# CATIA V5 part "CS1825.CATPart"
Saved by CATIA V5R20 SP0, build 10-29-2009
Part number: CS1825
Revision: 4
Definition: design
Nomenclature: CS1825
Source: made
Description: NOT SPECIFIED
Bounding box of the stored display mesh (mm): x -23.825 to 24, y -24 to 24, z -45 to 12
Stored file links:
  C:\Users\Raffaele\Desktop\3D X SITO CF\BOLEX\20-TILTED COLUMN SUPPORT\CS1825.CATPart
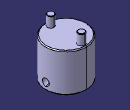
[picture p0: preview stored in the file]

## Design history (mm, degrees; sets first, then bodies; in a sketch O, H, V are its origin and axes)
Body1 "MANIFOLD_SOLID_BREP #711" (main body)
  Solid1: solid without history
